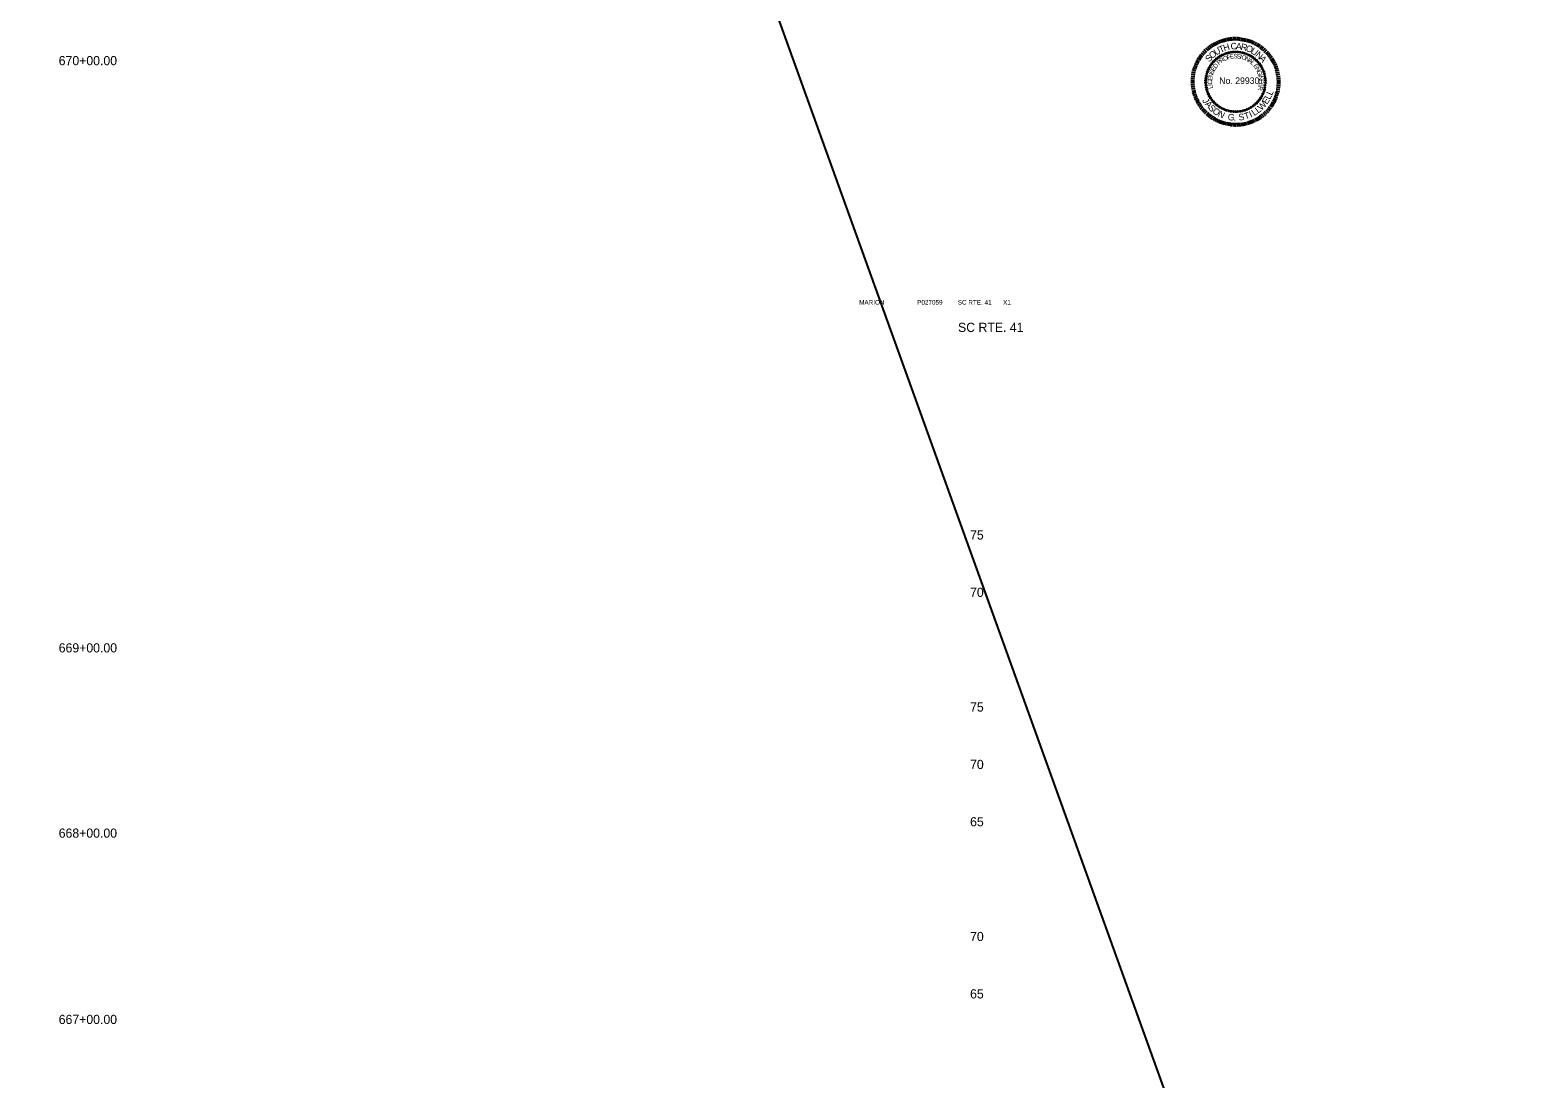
# Model space of a CAD drawing. Extents: x 952 to 1206, y 942 to 2399.
# Drawn here: x 1074.9 to 1206.4, y 1033 to 1124.4 of the extents above; entities that cross this region are included whole.
import ezdxf

# ---------------------------------------------------------------- set-up
doc = ezdxf.new("R2010")
doc.units = 0
for name, color, linetype in [('Default', 7, 'Continuous'), ('RD_SHT_TX', 7, 'Continuous'), ('RD_TX_PEShield', 7, 'Continuous'), ('RD_XS_TX_Elev_EX', 7, 'Continuous'), ('RD_XS_TX_Station', 7, 'Continuous')]:
    doc.layers.add(name, color=color, linetype=linetype)

# ---------------------------------------------------------------- blocks, each defined once
blk = doc.blocks.new('STILLWELL')
at = {"layer": 'RD_TX_PEShield'}
for p, q in [((-25.1, 24.7), (-27.4, 27.1)), ((-23.8, 25.9), (-26, 28.4)), ((-22.5, 27), (-24.5, 29.6)), ((-21.1, 28.1), (-23, 30.7)), ((-19.7, 29.1), (-21.5, 31.8)), ((-18.2, 30), (-19.9, 32.8)), ((-16.7, 30.8), (-18.2, 33.7)), ((-15.1, 31.6), (-16.5, 34.6)), ((-13.6, 32.3), (-14.8, 35.3)), ((-11.9, 32.9), (-13, 36)), ((-10.3, 33.4), (-11.2, 36.6)), ((-8.6, 33.9), (-9.4, 37.1)), ((-6.9, 34.3), (-7.5, 37.5)), ((-5.2, 34.6), (-5.7, 37.8)), ((-3.5, 34.8), (-3.8, 38)), ((-1.8, 34.9), (-1.9, 38.2)), ((0, 34.9), (0, 38.2)), ((1.7, 34.9), (1.9, 38.2)), ((3.4, 34.8), (3.7, 38)), ((5.2, 34.6), (5.6, 37.8)), ((6.9, 34.3), (7.5, 37.5)), ((8.6, 33.9), (9.3, 37.1)), ((10.2, 33.4), (11.2, 36.6)), ((11.9, 32.9), (13, 36)), ((13.5, 32.3), (14.7, 35.3)), ((15.1, 31.6), (16.5, 34.6)), ((16.6, 30.8), (18.2, 33.7)), ((18.2, 30), (19.8, 32.8)), ((19.6, 29.1), (21.4, 31.8)), ((21.1, 28.1), (23, 30.7)), ((22.4, 27), (24.5, 29.6)), ((23.8, 25.9), (25.9, 28.4)), ((25, 24.7), (27.3, 27.1)), ((-32.9, 13.4), (-35.9, 14.7)), ((-32.2, 15), (-35.1, 16.4)), ((-31.4, 16.5), (-34.2, 18.1)), ((-30.5, 18), (-33.3, 19.7)), ((-29.5, 19.4), (-32.2, 21.3)), ((-28.5, 20.9), (-31.1, 22.8)), ((-27.4, 22.2), (-29.9, 24.3)), ((-26.3, 23.5), (-28.7, 25.7)), ((26.2, 23.5), (28.6, 25.7)), ((27.4, 22.2), (29.9, 24.3)), ((28.5, 20.9), (31.1, 22.8)), ((29.5, 19.4), (32.2, 21.3)), ((30.4, 18), (33.2, 19.7)), ((31.3, 16.5), (34.2, 18.1)), ((32.1, 15), (35.1, 16.4)), ((32.9, 13.4), (35.9, 14.7)), ((-35.9, -0.1), (-39.2, 0)), ((-35.8, 1.7), (-39.1, 1.9)), ((-35.6, 3.4), (-38.9, 3.8)), ((-35.4, 5.1), (-38.6, 5.7)), ((-35.1, 6.8), (-38.2, 7.5)), ((-34.6, 8.5), (-37.8, 9.4)), ((-34.1, 10.2), (-37.2, 11.2)), ((-33.6, 11.8), (-36.6, 12.9)), ((33.5, 11.8), (36.6, 12.9)), ((34.1, 10.2), (37.2, 11.2)), ((34.6, 8.5), (37.7, 9.4)), ((35, 6.8), (38.2, 7.5)), ((35.3, 5.1), (38.5, 5.7)), ((35.6, 3.4), (38.8, 3.8)), ((35.7, 1.7), (39, 1.9)), ((35.8, -0.1), (39.1, 0)), ((-35.9, -1.8), (-39.2, -1.9)), ((-35.8, -3.5), (-39.1, -3.8)), ((-35.6, -5.3), (-38.9, -5.6)), ((-35.4, -7), (-38.6, -7.5)), ((-35.1, -8.7), (-38.2, -9.4)), ((-34.6, -10.4), (-37.8, -11.2)), ((-34.1, -12), (-37.2, -13)), ((34.1, -12), (37.2, -13)), ((34.6, -10.4), (37.7, -11.2)), ((35, -8.7), (38.2, -9.4)), ((35.3, -7), (38.5, -7.5)), ((35.6, -5.3), (38.8, -5.6)), ((35.7, -3.5), (39, -3.8)), ((35.8, -1.8), (39.1, -1.9)), ((-33.6, -13.6), (-36.6, -14.8)), ((-32.9, -15.3), (-35.9, -16.6)), ((-32.2, -16.8), (-35.1, -18.3)), ((-31.4, -18.4), (-34.2, -19.9)), ((-30.5, -19.9), (-33.3, -21.6)), ((-29.5, -21.3), (-32.2, -23.2)), ((-28.5, -22.7), (-31.1, -24.7)), ((-27.4, -24.1), (-29.9, -26.2)), ((-26.3, -25.4), (-28.7, -27.6)), ((26.2, -25.4), (28.6, -27.6)), ((27.4, -24.1), (29.9, -26.2)), ((28.5, -22.7), (31.1, -24.7)), ((29.5, -21.3), (32.2, -23.2)), ((30.4, -19.9), (33.2, -21.6)), ((31.3, -18.4), (34.2, -19.9)), ((32.1, -16.8), (35.1, -18.3)), ((32.9, -15.3), (35.9, -16.6)), ((33.5, -13.6), (36.6, -14.8)), ((-25.1, -26.6), (-27.4, -28.9)), ((-23.8, -27.8), (-26, -30.2)), ((-22.5, -28.9), (-24.5, -31.4)), ((-21.1, -29.9), (-23, -32.6)), ((-19.7, -30.9), (-21.5, -33.7)), ((-18.2, -31.8), (-19.9, -34.7)), ((-16.7, -32.7), (-18.2, -35.6)), ((-15.1, -33.5), (-16.5, -36.4)), ((-13.6, -34.1), (-14.8, -37.2)), ((-11.9, -34.8), (-13, -37.8)), ((-10.3, -35.3), (-11.2, -38.4)), ((-8.6, -35.8), (-9.4, -38.9)), ((-6.9, -36.1), (-7.5, -39.3)), ((-5.2, -36.4), (-5.7, -39.7)), ((-3.5, -36.6), (-3.8, -39.9)), ((-1.8, -36.8), (-1.9, -40)), ((0, -36.8), (0, -40.1)), ((1.7, -36.8), (1.9, -40)), ((3.4, -36.6), (3.7, -39.9)), ((5.2, -36.4), (5.6, -39.7)), ((6.9, -36.1), (7.5, -39.3)), ((8.6, -35.8), (9.3, -38.9)), ((10.2, -35.3), (11.2, -38.4)), ((11.9, -34.8), (13, -37.8)), ((13.5, -34.1), (14.7, -37.2)), ((15.1, -33.5), (16.5, -36.4)), ((16.6, -32.7), (18.2, -35.6)), ((18.2, -31.8), (19.8, -34.7)), ((19.6, -30.9), (21.4, -33.7)), ((21.1, -29.9), (23, -32.6)), ((22.4, -28.9), (24.5, -31.4)), ((23.8, -27.8), (25.9, -30.2)), ((25, -26.6), (27.3, -28.9))]:
    blk.add_line(p, q, dxfattribs=at)
for centre in [(-21.9, 13.2), (-20.7, 14.9), (-19.5, 16.4), (-18.1, 17.8), (-16.6, 19.2), (-15, 20.4), (-13.3, 21.5), (-11.6, 22.4), (-9.8, 23.2), (-7.9, 23.9), (-6, 24.4), (-4, 24.8), (-2, 25), (0, 25.1), (2, 25), (3.9, 24.8), (5.9, 24.4), (7.8, 23.9), (9.7, 23.2), (11.5, 22.4), (13.3, 21.5), (15, 20.4), (16.5, 19.2), (18, 17.8), (19.4, 16.4), (20.7, 14.9), (21.8, 13.2), (-26.1, 0.1), (-25.9, 2.1), (-25.6, 4), (-25.1, 6), (-24.5, 7.9), (-23.8, 9.7), (-22.9, 11.5), (22.9, 11.5), (23.7, 9.7), (24.5, 7.9), (25.1, 6), (25.5, 4), (25.8, 2.1), (26, 0.1), (-26.1, -1.9), (-25.9, -3.9), (-25.6, -5.9), (-25.1, -7.8), (-24.5, -9.7), (-23.8, -11.6), (-22.9, -13.4), (22.9, -13.4), (23.7, -11.6), (24.5, -9.7), (25.1, -7.8), (25.5, -5.9), (25.8, -3.9), (26, -1.9), (-21.9, -15.1), (-20.7, -16.7), (-19.5, -18.3), (-18.1, -19.7), (-16.6, -21), (-15, -22.2), (-13.3, -23.3), (-11.6, -24.3), (-9.8, -25.1), (-7.9, -25.8), (-6, -26.3), (-4, -26.7), (3.9, -26.7), (5.9, -26.3), (7.8, -25.8), (9.7, -25.1), (11.5, -24.3), (13.3, -23.3), (15, -22.2), (16.5, -21), (18, -19.7), (19.4, -18.3), (20.7, -16.7), (21.8, -15.1), (-2, -26.9), (0, -27), (2, -26.9)]:
    blk.add_circle(centre, 0.49, dxfattribs=at)
for s, height, rotation, p in [('U', 5.68, 32.2152, (-16.9, 21.8)), ('T', 5.68, 23.5044, (-13.2, 24.1)), ('H', 5.68, 16.1357, (-9.9, 25.6)), ('C', 5.68, 4.076, (-4.2, 27.1)), ('A', 5.68, 355.3651, (0.1, 27.4)), ('R', 5.68, 347.3188, (4.1, 27.1)), ('O', 5.68, 338.6079, (8.3, 26.2)), ('L', 5.68, 329.226, (12.6, 24.4)), ('I', 5.68, 322.5218, (15.5, 22.8)), ('S', 5.68, 49.6435, (-22.9, 15.8)), ('O', 5.68, 41.5972, (-20.4, 18.8)), ('D', 3.92, 52.5376, (-17.1, 10.3)), ('P', 3.92, 41.0022, (-14.5, 13.5)), ('R', 3.92, 33.3057, (-12.5, 15.3)), ('O', 3.92, 24.9735, (-10, 16.9)), ('F', 3.92, 15.9995, (-7.1, 18.3)), ('E', 3.92, 8.9511, (-4.7, 19)), ('S', 3.92, 1.2546, (-1.9, 19.4)), ('S', 3.92, 353.558, (0.8, 19.5)), ('I', 3.92, 345.8615, (3.5, 19.2)), ('O', 3.92, 342.6583, (4.7, 19)), ('N', 3.92, 333.6842, (7.7, 18)), ('A', 3.92, 325.3521, (10.4, 16.7)), ('L', 3.92, 317.6555, (12.6, 15.1)), ('E', 3.92, 308.0396, (15.1, 12.8)), ('N', 5.68, 319.1729, (16.8, 21.8)), ('A', 5.68, 310.4621, (20.1, 19)), ('C', 3.92, 92.2915, (-20.4, -3.2)), ('E', 3.92, 83.9594, (-20.5, -0.2)), ('N', 3.92, 76.2628, (-20.2, 2.5)), ('S', 3.92, 67.9307, (-19.5, 5.4)), ('E', 3.92, 60.2341, (-18.5, 7.9)), ('N', 3.92, 300.343, (16.8, 10.6)), ('G', 3.92, 292.0109, (18.3, 8.1)), ('I', 3.92, 283.0368, (19.5, 5.1)), ('N', 3.92, 279.8336, (19.8, 4)), ('E', 3.92, 271.5014, (20.3, 1.1)), ('I', 3.92, 95.4947, (-20.2, -4.3)), ('L', 3.92, 101.9075, (-19.7, -6.6)), ('R', 3.92, 256.1083, (20.1, -4.4)), ('E', 3.92, 263.8049, (20.4, -1.7)), ('L', 5.68, 65.098, (30, -16.9)), ('L', 5.68, 65.098, (31.6, -13.3)), ('J', 5.68, 299.033, (-29.4, -17.3)), ('A', 5.68, 310.5887, (-27.2, -20.6)), ('S', 5.68, 310.5887, (-24.3, -24)), ('O', 5.68, 321.0072, (-20.8, -27.4)), ('N', 5.68, 333.4326, (-16, -30.8)), ('L', 5.68, 34.0644, (16.2, -30.9)), ('L', 5.68, 37.6708, (19.6, -28.7)), ('W', 5.68, 47.0518, (22.6, -26.4)), ('E', 5.68, 56.4327, (27.3, -21.1)), ('G', 5.68, 352.2045, (-7.2, -34.2)), ('.', 5.68, 0.8698, (-1.8, -34.9)), ('S', 5.68, 8.0826, (2.9, -34.8)), ('T', 5.68, 18.9019, (8.5, -33.9)), ('I', 5.68, 25.3991, (13.3, -32.2))]:
    blk.add_text(s, height=height, rotation=rotation, dxfattribs=at).set_placement(p)
blk.add_text('No. 29930', height=5.68, dxfattribs=at).set_placement((-14.3, -2.8))

msp = doc.modelspace()

# ---------------------------------------------------------------- linework, layer by layer
at = {"layer": 'RD_SHT_TX'}
msp.add_line((980.77, 1567.94), (1206.44, 941.58), dxfattribs=at)

# ---------------------------------------------------------------- block references
at = {"layer": 'Default', "xscale": 0.1, "yscale": 0.10000000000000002}
msp.add_blockref('STILLWELL', (1180.08, 1120), dxfattribs=at)

# ---------------------------------------------------------------- texts
at = {"layer": 'RD_SHT_TX'}
for s, height, p in [('MARION', 0.4, (1147.25, 1100.48)), ('P027059', 0.4, (1152.31, 1100.48)), ('SC RTE. 41', 0.4, (1155.85, 1100.48)), ('X1', 0.4, (1159.8, 1100.48)), ('SC RTE. 41', 0.8, (1155.87, 1098.1))]:
    msp.add_text(s, height=height, dxfattribs=at).set_placement(p)
at = {"layer": 'RD_XS_TX_Elev_EX'}
for s, p in [('75', (1156.92, 1080)), ('70', (1156.92, 1075)), ('75', (1156.92, 1065)), ('70', (1156.92, 1060)), ('65', (1156.92, 1055)), ('70', (1156.92, 1045)), ('65', (1156.92, 1040))]:
    msp.add_text(s, height=0.8, dxfattribs=at).set_placement(p)
at = {"layer": 'RD_XS_TX_Station'}
for s, p in [('670+00.00', (1077.44, 1121.35)), ('669+00.00', (1077.44, 1070.16)), ('668+00.00', (1077.44, 1054.01)), ('667+00.00', (1077.44, 1037.77))]:
    msp.add_text(s, height=0.8, dxfattribs=at).set_placement(p)

doc.saveas('drawing.dxf')
